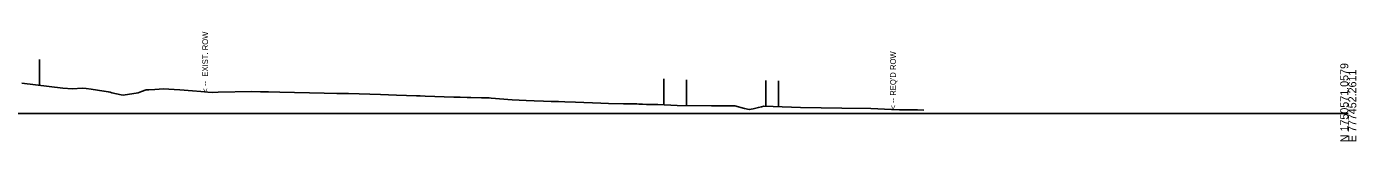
# Model space of a CAD drawing. Extents: x 776426 to 854588, y 1736205 to 1756790.
# Drawn here: x 805208.3 to 805673.6, y 1752205.1 to 1752243.4 of the extents above; entities that cross this region are included whole.
import ezdxf

# ---------------------------------------------------------------- set-up
doc = ezdxf.new("R2010")
doc.units = 0
for name, color, linetype in [('63', 7, 'Continuous'), ('DTM CONTOURS_MAJOR_TX', 7, 'Continuous'), ('DTM_X_FLOW_ARROWS', 7, 'Continuous'), ('TRANS_EOP_PAVED', 7, 'Continuous'), ('TRANS_UNPAVED_SHOULDERS', 7, 'Continuous'), ('XS_P_ROW', 7, 'Continuous'), ('XS_X_ROW', 7, 'Continuous')]:
    doc.layers.add(name, color=color, linetype=linetype)

msp = doc.modelspace()

# ---------------------------------------------------------------- linework, layer by layer
at = {"layer": '63'}
msp.add_line((805212.81, 1752233.66), (805212.81, 1752224.66), dxfattribs=at)
msp.add_line((805212.81, 1752233.66), (805212.81, 1752224.66), dxfattribs=at)
at = {"layer": 'DTM CONTOURS_MAJOR_TX'}
msp.add_line((805170.79, 1752214.76), (805670.79, 1752214.76), dxfattribs=at)
at = {"layer": 'DTM_X_FLOW_ARROWS'}
msp.add_lwpolyline([(805206.67, 1752225.37), (805221.06, 1752223.7), (805224.41, 1752223.48), (805227.76, 1752223.65), (805229.15, 1752223.6), (805230.9, 1752223.32), (805235.42, 1752222.66), (805236.95, 1752222.34), (805237.55, 1752222.22), (805238.18, 1752222.08), (805241.4, 1752221.38), (805242.1, 1752221.22), (805247.41, 1752222.01), (805248.61, 1752222.48), (805250.13, 1752223.07), (805251.17, 1752223.11), (805253.26, 1752223.2), (805256.24, 1752223.46), (805260.03, 1752223.2), (805261.92, 1752223.04), (805266.38, 1752222.77), (805269.34, 1752222.55), (805271.75, 1752222.24), (805273.55, 1752222.16), (805275.39, 1752222.21), (805287.21, 1752222.45), (805290.2, 1752222.41), (805291.04, 1752222.41), (805291.78, 1752222.39), (805293.04, 1752222.38), (805296.96, 1752222.3), (805312.42, 1752221.89), (805316.94, 1752221.77), (805318.78, 1752221.78), (805321.02, 1752221.77), (805332.2, 1752221.48), (805337.79, 1752221.2), (805344.77, 1752220.93), (805346.05, 1752220.93), (805347.76, 1752220.89), (805357.78, 1752220.5), (805358.68, 1752220.51), (805360.08, 1752220.49), (805362.51, 1752220.43), (805363.78, 1752220.41), (805367.47, 1752220.27), (805370.23, 1752220.31), (805370.88, 1752220.22), (805378.25, 1752219.57), (805383.13, 1752219.34), (805385.96, 1752219.18), (805389.17, 1752219.12), (805391.94, 1752219.05), (805394.49, 1752219), (805396.64, 1752218.89), (805400.43, 1752218.76), (805409.31, 1752218.47), (805411.91, 1752218.36), (805417.16, 1752218.24), (805421.84, 1752218.14), (805422.58, 1752218.09), (805423.27, 1752218.06), (805423.9, 1752218.03), (805425.26, 1752218.01), (805426.55, 1752218.01), (805429.2, 1752217.99), (805436.01, 1752217.61), (805447.96, 1752217.5), (805450.61, 1752217.45), (805453.04, 1752217.47), (805456.11, 1752217.5), (805459.57, 1752216.61), (805461.19, 1752216.18), (805462.62, 1752216.48), (805464.4, 1752216.92), (805465.54, 1752217.19), (805466.24, 1752217.33), (805475.94, 1752217.04), (805479.09, 1752216.93), (805493.63, 1752216.71), (805503.68, 1752216.53), (805510.97, 1752216.19), (805513.82, 1752216.1), (805520.02, 1752216.04), (805522.32, 1752215.97)], dxfattribs=at)
at = {"layer": 'TRANS_EOP_PAVED'}
for p, q in [((805439.29, 1752226.58), (805439.29, 1752217.58)), ((805439.29, 1752226.58), (805439.29, 1752217.58)), ((805466.97, 1752226.31), (805466.97, 1752217.31)), ((805466.97, 1752226.31), (805466.97, 1752217.31))]:
    msp.add_line(p, q, dxfattribs=at)
at = {"layer": 'TRANS_UNPAVED_SHOULDERS'}
for p, q in [((805431.27, 1752226.87), (805431.27, 1752217.87)), ((805431.27, 1752226.87), (805431.27, 1752217.87)), ((805471.38, 1752226.18), (805471.38, 1752217.18)), ((805471.38, 1752226.18), (805471.38, 1752217.18))]:
    msp.add_line(p, q, dxfattribs=at)

# ---------------------------------------------------------------- texts
at = {"layer": 'DTM CONTOURS_MAJOR_TX'}
for s, p in [('N 1750571.0579', (805670.79, 1752204.76)), ('E 777452.2611', (805673.59, 1752204.76))]:
    msp.add_text(s, height=2.8, rotation=90, dxfattribs=at).set_placement(p)
at = {"layer": 'XS_P_ROW'}
msp.add_text("< -- REQ'D ROW", height=2, rotation=90, dxfattribs=at).set_placement((805512.5, 1752216.18))
at = {"layer": 'XS_X_ROW'}
msp.add_text('< --  EXIST. ROW', height=2, rotation=90, dxfattribs=at).set_placement((805271.83, 1752222.11))

doc.saveas('drawing.dxf')
